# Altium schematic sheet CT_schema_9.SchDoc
size 274 x 160 mm
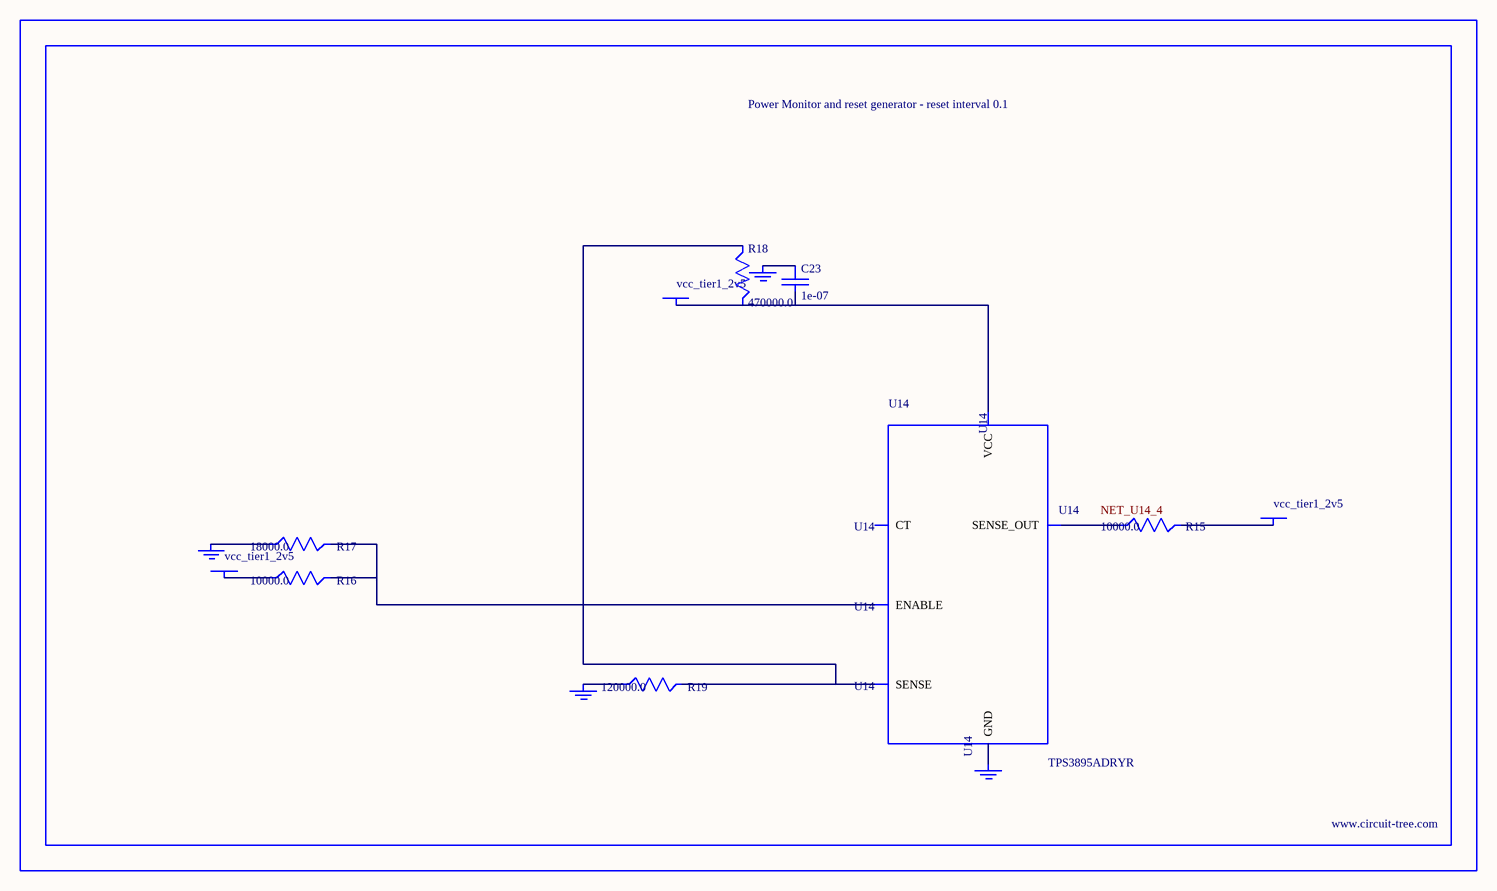
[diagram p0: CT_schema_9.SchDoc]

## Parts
BORDER8  (no value)
C23  1e-07  [C0402]
GND_INSTANCE_8_0  (no value)
GND_INSTANCE_8_1  (no value)
GND_INSTANCE_8_2  (no value)
GND_INSTANCE_8_3  (no value)
POWER_INSTANCE_8_0  vcc_tier1_2v5
POWER_INSTANCE_8_1  vcc_tier1_2v5
POWER_INSTANCE_8_2  vcc_tier1_2v5
R15  10000.0  [R0603]
R16  10000.0  [R0603]
R17  18000.0  [R0603]
R18  470000.0  [R0603]
R19  120000.0  [R0603]
U14  TPS3895ADRYR  [SON-6]

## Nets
NetC23_1: C23.1 GND_INSTANCE_8_2.0(GND)
NetC23_2: C23.2 POWER_INSTANCE_8_2.0(PWR) R18.2 U14.6(VCC)
NetGND_INSTANCE_8_0_0: GND_INSTANCE_8_0.0(GND) R17.1
NetGND_INSTANCE_8_1_0: GND_INSTANCE_8_1.0(GND) R19.1
NetGND_INSTANCE_8_3_0: GND_INSTANCE_8_3.0(GND) U14.2(GND)
NetPOWER_INSTANCE_8_0_0: POWER_INSTANCE_8_0.0(PWR) R16.1
NetPOWER_INSTANCE_8_1_0: POWER_INSTANCE_8_1.0(PWR) R15.2
NetR15_1: R15.1 U14.4(SENSE_OUT)
NetR16_2: R16.2 R17.2 U14.1(ENABLE)
NetR18_1: R18.1 R19.2 U14.3(SENSE)

Not connected (* = marked no-connect by the designer): U14 5(CT)

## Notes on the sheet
- Labels drawn without touching a wire or pin: NET_U14_4

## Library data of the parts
BORDER8 = BORDER_PAGE8
C23 = C0402C104K3RACTU
GND_INSTANCE_8_0-GND_INSTANCE_8_3 = GND
POWER_INSTANCE_8_0-POWER_INSTANCE_8_2 = PWR
R15 R16 = RC0603JR-0710KL
R17 = RC0603JR-0718KL
R18 = RC0603JR-07470KL
R19 = RC0603JR-07120KL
